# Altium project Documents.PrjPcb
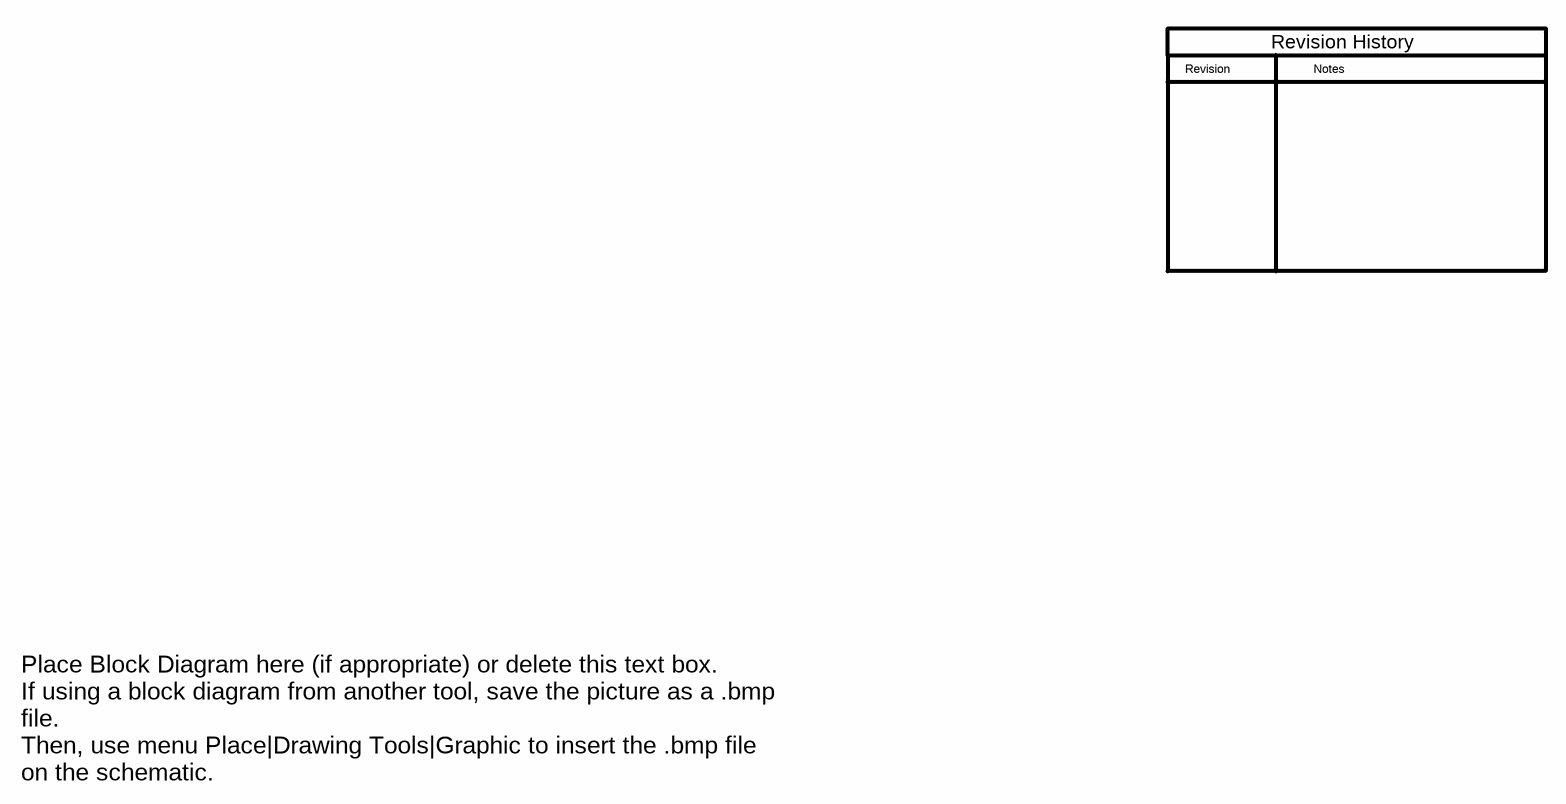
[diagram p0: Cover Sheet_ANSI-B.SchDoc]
CopyrightYear: 2014; PCB_Layout: Who did the Layout?; PCB_Rev: E1; PRJ_Customer: Public Release; PRJ_Engineer: Enter name of project lead; PRJ_Number: XX####; PRJ_Title: Change in menu Project|Project Options|Parameters; SCH_Rev: E1; TechSupport: http://www.ti.com/support
3 sheets, 22 parts. Net scope: global (net labels, ports and power ports of the same name join across sheets).
Board file: xxxxxx.PcbDoc
Sheets:
  Cover Sheet_ANSI-B.SchDoc
  BlankSheet_ANSI-B.SchDoc
  Hardware_ANSI-B.SchDoc

## Sheet Cover Sheet_ANSI-B.SchDoc
size 431 x 279 mm; Date: Not shown in title block; ApprovedBy: Not shown in title block; CheckedBy: Not shown in title block; Author: Not shown in title block; CompanyName: Not shown in title block; Engineer: Not shown in title block; Organization: Not shown in title block; Address1: Not shown in title block; Address2: Not shown in title block; Address3: Not shown in title block; Address4: Not shown in title block; DocumentNumber: 1; Revision: Use project parameter SCH_Rev; SheetNumber: 1; SheetTotal: 1; PageSetup: Record=PageOptions|CenterHorizontal=True|CenterVertical=True|PrintScale=1.00|XCorrection=1.00|YCorrection=1.00|PrintKind=0|BorderSize=5000000|LeftOffset=0|BottomOffset=0|Orientation=2|PaperLength=1000|PaperWidth=1000|Scale=100|PaperSource=15|PrintQuality=600|MediaType=1|DitherType=10|PaperKind=Letter|PrintScaleMode=1

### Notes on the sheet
- Revision
- Notes
- Revision History
- Place Block Diagram here (if appropriate) or delete this text box.
  If using a block diagram from another tool, save the picture as a .bmp file.
  Then, use menu Place|Drawing Tools|Graphic to insert the .bmp file on the schematic.

## Sheet BlankSheet_ANSI-B.SchDoc
size 431 x 279 mm; Date: Not shown in title block; ApprovedBy: Not shown in title block; CheckedBy: Not shown in title block; Author: Not shown in title block; CompanyName: Not shown in title block; Engineer: Not shown in title block; Organization: Not shown in title block; Address1: Not shown in title block; Address2: Not shown in title block; Address3: Not shown in title block; Address4: Not shown in title block; DocumentNumber: 1; Revision: Use project parameter SCH_Rev; SheetNumber: 1; SheetTotal: 1; PageSetup: Record=PageOptions|CenterHorizontal=True|CenterVertical=True|PrintScale=1.00|XCorrection=1.00|YCorrection=1.00|PrintKind=0|BorderSize=5000000|LeftOffset=0|BottomOffset=0|Orientation=2|PaperLength=1000|PaperWidth=1000|Scale=100|PaperSource=15|PrintQuality=600|MediaType=1|DitherType=10|PaperKind=Letter|PrintScaleMode=1

## Sheet Hardware_ANSI-B.SchDoc
size 431 x 279 mm; Date: Not shown in title block; ApprovedBy: Not shown in title block; CheckedBy: Not shown in title block; Author: Not shown in title block; CompanyName: Not shown in title block; Engineer: Not shown in title block; Organization: Not shown in title block; Address1: Not shown in title block; Address2: Not shown in title block; Address3: Not shown in title block; Address4: Not shown in title block; DocumentNumber: 1; Revision: Use project parameter SCH_Rev; SheetNumber: 1; SheetTotal: 1; PageSetup: Record=PageOptions|CenterHorizontal=True|CenterVertical=True|PrintScale=1.00|XCorrection=1.00|YCorrection=1.00|PrintKind=0|BorderSize=5000000|LeftOffset=0|BottomOffset=0|Orientation=2|PaperLength=1000|PaperWidth=1000|Scale=100|PaperSource=15|PrintQuality=600|MediaType=1|DitherType=10|PaperKind=Letter|PrintScaleMode=1
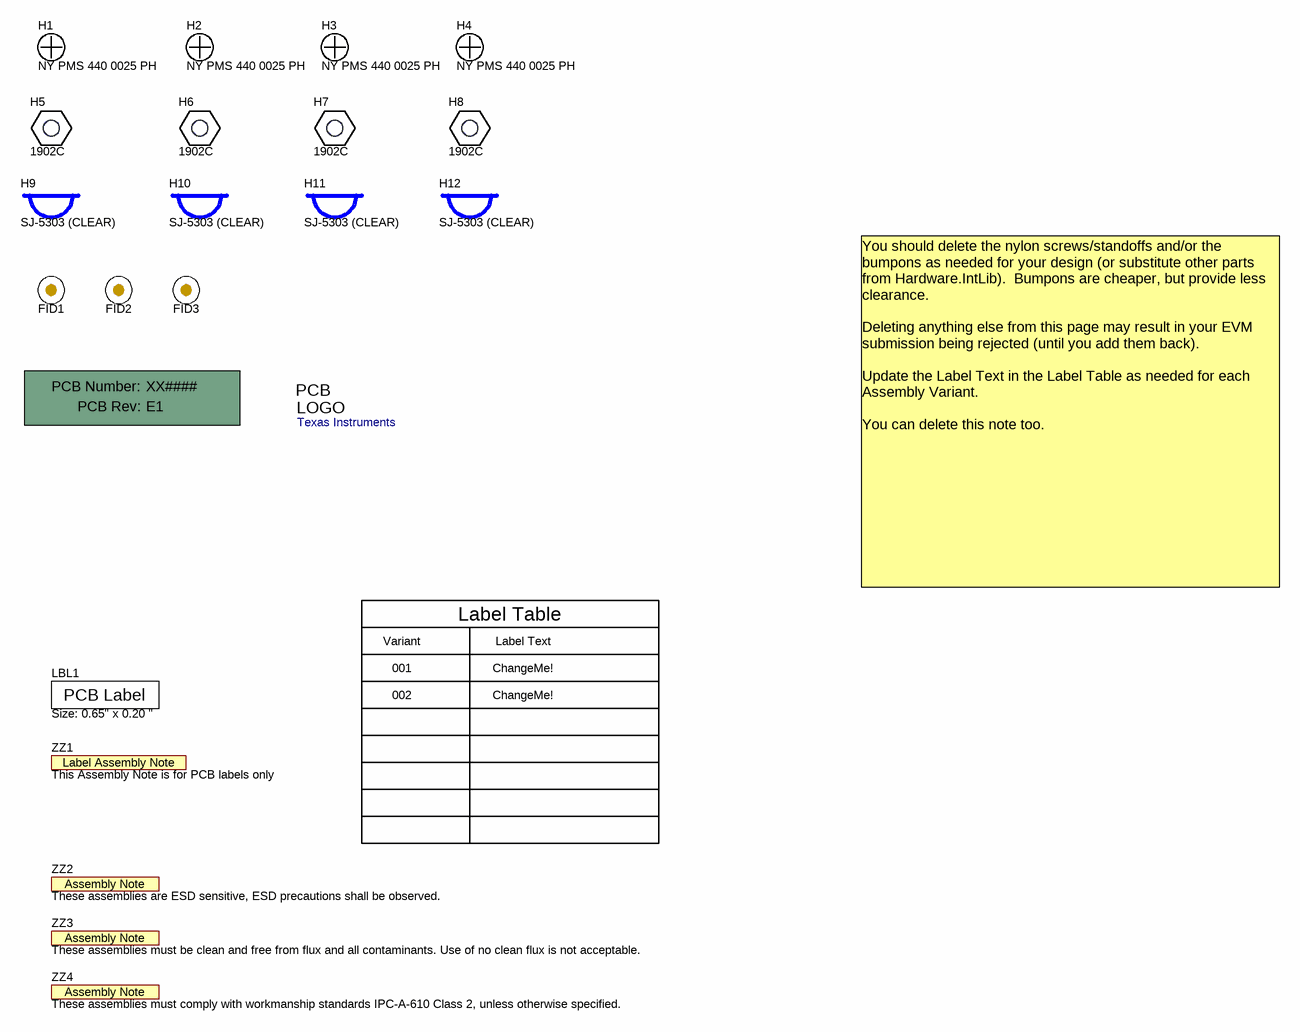
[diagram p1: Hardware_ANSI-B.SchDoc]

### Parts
!PCB  Printed Circuit Board  (value not drawn)  (mechanical)
FID1  Fiducial  [Fiducial10-20]  (value not drawn)
FID2  Fiducial  [Fiducial10-20]  (value not drawn)
FID3  Fiducial  [Fiducial10-20]  (value not drawn)
H1  NY PMS 440 0025 PH  [NY PMS 440 0025 PH]
H2  NY PMS 440 0025 PH  [NY PMS 440 0025 PH]
H3  NY PMS 440 0025 PH  [NY PMS 440 0025 PH]
H4  NY PMS 440 0025 PH  [NY PMS 440 0025 PH]
H5  1902C  [Keystone_1902C]
H6  1902C  [Keystone_1902C]
H7  1902C  [Keystone_1902C]
H8  1902C  [Keystone_1902C]
H9  SJ-5303 (CLEAR)  [Bumpon_SJ5003Transparent]
H10  SJ-5303 (CLEAR)  [Bumpon_SJ5003Transparent]
H11  SJ-5303 (CLEAR)  [Bumpon_SJ5003Transparent]
H12  SJ-5303 (CLEAR)  [Bumpon_SJ5003Transparent]
LBL1  Size: 0.65" x 0.20 "  [Label_650x200]
Logo1  Texas Instruments  [TI_Stacked_SolderMask_Small]  (no BOM)
ZZ1  This Assembly Note is for PCB labels only  [AssemblyNoteLabel]  (no BOM)
ZZ2  These assemblies are ESD sensitive, ESD precautions shall be observed.  [AssemblyNote]  (no BOM)
ZZ3  These assemblies must be clean and free from flux and all contaminants. Use of no clean flux is not acceptable.  [AssemblyNote]  (no BOM)
ZZ4  These assemblies must comply with workmanship standards IPC-A-610 Class 2, unless otherwise specified.  [AssemblyNote]  (no BOM)

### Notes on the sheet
- Variant
- Label Table
- Label Text
- You should delete the nylon screws/standoffs and/or the bumpons as needed for your design (or substitute other parts from Hardware.IntLib).  Bumpons are cheaper, but provide less clearance.
  Deleting anything else from this page may result in your EVM submission being rejected (until you add them back).
  Update the Label Text in the Label Table as needed for each Assembly Variant.
  You can delete this note too.
- 001
- 002
- ChangeMe!

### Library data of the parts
!PCB = PCB: Manufacturer: Any; PartNumber: XX####; SymbolCreator: a0412235
FID1-FID3 = Fiducial: Fiducial mark.  There is nothing to buy or mount.; SymbolCreator: codlsc
H1-H4 = NY PMS 440 0025 PH: Machine Screw, Round, #4-40 x 1/4, Nylon, Philips panhead; Manufacturer: B&F Fastener Supply; CompType: Hardware; SymbolCreator: codlsc; U/M: EA
H5-H8 = 1902C: Standoff, Hex, 0.5"L #4-40 Nylon; Manufacturer: Keystone; CompType: Hardware; SymbolCreator: a0412235
H9-H12 = SJ-5303 (CLEAR): Bumpon, Hemisphere, 0.44 X 0.20, Clear; Manufacturer: 3M; SymbolCreator: a0412235
LBL1 = THT-14-423-10: Thermal Transfer Printable Labels, 0.650" W x 0.200" H - 10,000 per roll; Manufacturer: Brady; SymbolCreator: a0412235; CompType: Label
Logo1 = TI_Logo: Texas Instrument Corporate Signature; SymbolCreator: a0412235
ZZ1 = AssemblyNoteLabel: SymbolCreator: a0412235
ZZ2-ZZ4 = AssemblyNote: SymbolCreator: codlsc

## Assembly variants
001: not fitted FID1 FID2 FID3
